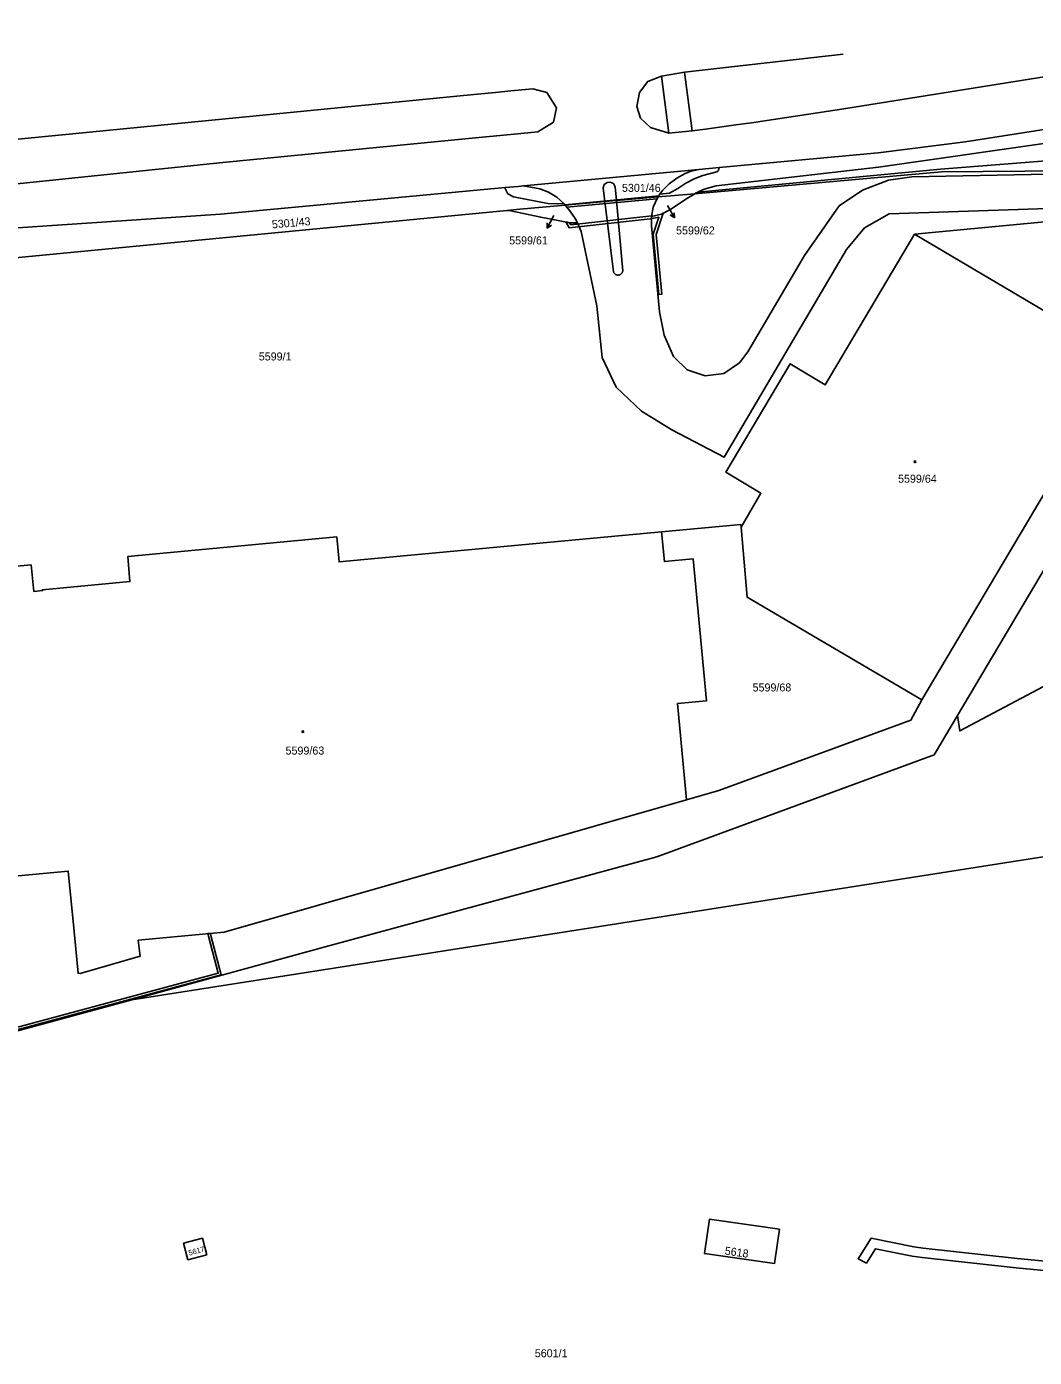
# Model space of a CAD drawing. Extents: x -821458 to -820266, y -1071458 to -1069826.
# Drawn here: x -821204.8 to -820990.7, y -1070118.4 to -1069835.7 of the extents above; entities that cross this region are included whole.
import ezdxf

# ---------------------------------------------------------------- set-up
doc = ezdxf.new("R2010")
doc.units = 0
for name, color, linetype in [('Vrstva 1', 7, 'Continuous'), ('Vrstva 13', 7, 'Continuous'), ('Vrstva 2', 7, 'Continuous'), ('Vrstva 4', 7, 'Continuous'), ('Vrstva 5', 7, 'Continuous'), ('Vrstva 7', 7, 'Continuous')]:
    doc.layers.add(name, color=color, linetype=linetype)

msp = doc.modelspace()

# ---------------------------------------------------------------- linework, layer by layer
at = {"layer": 'Vrstva 1'}
for p, q in [((-821061.99, -1069866.11), (-821099.18, -1069869.56)), ((-821070.6, -1069871.92), (-821070.81, -1069872.22)), ((-821062.78, -1069871.23), (-821070.6, -1069871.92)), ((-821070.6, -1069871.92), (-821070.22, -1069871.36)), ((-821064.36, -1069872.17), (-821062.78, -1069871.23)), ((-821062.78, -1069871.23), (-821062.64, -1069871.14)), ((-821102.76, -1069874.78), (-821099.96, -1069874.51)), ((-821099.96, -1069874.51), (-821090.34, -1069873.66)), ((-821090.34, -1069873.66), (-821090.39, -1069873.6)), ((-821090, -1069874.09), (-821090.34, -1069873.66)), ((-820971.6, -1069906.22), (-821016.17, -1069879.84)), ((-821014.57, -1069978.75), (-820971.6, -1069906.22)), ((-821007, -1069982.04), (-820972.32, -1069923.54)), ((-821182.41, -1070042.44), (-821234.69, -1070056.69))]:
    msp.add_line(p, q, dxfattribs=at)
for points in [[(-821031.28, -1069841.61), (-821065.02, -1069845.45), (-821069.86, -1069846.25), (-821072.8, -1069847.42), (-821074.6, -1069849.74), (-821075.16, -1069852.74), (-821074.35, -1069855.22), (-821072.23, -1069857.2), (-821068.35, -1069858.38), (-821063.36, -1069857.88), (-821060.54, -1069857.49), (-821058.58, -1069857.22), (-821054.1, -1069856.61), (-821050.74, -1069856.15), (-821032.05, -1069853.34), (-821030.77, -1069853.1), (-820959.33, -1069841.72), (-820932.12, -1069837.86), (-820909.53, -1069835.76), (-820877.6, -1069835.74), (-820862.85, -1069836.75)], [(-821061.99, -1069866.11), (-821057.61, -1069865.7), (-821023.88, -1069862.57), (-821005.41, -1069860.19), (-820984.58, -1069856.94), (-820980.88, -1069855.59), (-820969.65, -1069851.52), (-820931.42, -1069845.82), (-820917.79, -1069844.37), (-820894.09, -1069843.23), (-820880.46, -1069843.52), (-820874.49, -1069844.42), (-820869.29, -1069844.79)], [(-821401.79, -1069888.55), (-821396.38, -1069888.03), (-821301.11, -1069878.88), (-821163.06, -1069864.6), (-821108.67, -1069859.31), (-821104.19, -1069858.87), (-821101.19, -1069858.58), (-821096.14, -1069858.08), (-821092.87, -1069856.06), (-821092.18, -1069852.96), (-821094.27, -1069849.73), (-821097.25, -1069848.99), (-821101.9, -1069849.39), (-821105.19, -1069849.71), (-821109.73, -1069850.16), (-821251.45, -1069864.02), (-821303.1, -1069868.83), (-821318.66, -1069870.67)], [(-821062.64, -1069871.14), (-821062.15, -1069870.91), (-821010.61, -1069866.01), (-820904.63, -1069857.69)], [(-820937.16, -1069864.21), (-820966.1, -1069866.2), (-821010.4, -1069866.6), (-821062.78, -1069871.23)], [(-821070.22, -1069871.36), (-821069.67, -1069870.57), (-821068.25, -1069869.11), (-821066.65, -1069867.91), (-821064.88, -1069866.94), (-821063.58, -1069866.45), (-821061.99, -1069866.11)], [(-821099.18, -1069869.56), (-821100.33, -1069869.67), (-821103.12, -1069869.93), (-821163.58, -1069875.55), (-821210.97, -1069878.75)], [(-821090.39, -1069873.6), (-821090.63, -1069873.3), (-821092.16, -1069871.98), (-821093.88, -1069870.91), (-821095.75, -1069870.17), (-821099.18, -1069869.56)], [(-821090.34, -1069873.66), (-821081.94, -1069872.92), (-821079.48, -1069872.7), (-821070.6, -1069871.92)], [(-821070.81, -1069872.22), (-821071.65, -1069874.06), (-821072.01, -1069876.04), (-821069.91, -1069875.59), (-821068.14, -1069874.64), (-821064.36, -1069872.17)], [(-821209.14, -1069885.06), (-821204.97, -1069884.66), (-821102.76, -1069874.78)], [(-821102.76, -1069874.78), (-821101.88, -1069874.89), (-821095.54, -1069876.23), (-821089.29, -1069877.41), (-821087.76, -1069877.41), (-821088.24, -1069876.51), (-821089.38, -1069874.86), (-821090, -1069874.09)], [(-820971.6, -1069906.22), (-820961.64, -1069889.6), (-820963.06, -1069874.82), (-821016.17, -1069879.84)], [(-821016.17, -1069879.84), (-821035.11, -1069911.83), (-821042.56, -1069907.36), (-821056.22, -1069930.41), (-821048.76, -1069934.85), (-821053, -1069942.05)], [(-821069.9, -1069943.03), (-821138.37, -1069949.45), (-821138.89, -1069944.15), (-821183.29, -1069948.31), (-821182.81, -1069953.61), (-821201.39, -1069955.37), (-821201.37, -1069955.54), (-821203.25, -1069955.71), (-821203.8, -1069950.08), (-821242.45, -1069953.67)], [(-821053, -1069942.05), (-821053.05, -1069941.49), (-821069.9, -1069943.03)], [(-821064.55, -1069999.98), (-821066.46, -1069979.54), (-821060.35, -1069978.98), (-821063.18, -1069948.76), (-821069.29, -1069949.37), (-821069.9, -1069943.03)], [(-821053, -1069942.05), (-821051.71, -1069956.95), (-821014.57, -1069978.75)], [(-820943.38, -1069944.62), (-820959, -1069957.1), (-820978.04, -1069970.23), (-821006.55, -1069985.33), (-821007, -1069982.04)], [(-821064.55, -1069999.98), (-821057.7, -1069997.97), (-821016.95, -1069983.03), (-821014.57, -1069978.75)], [(-821007, -1069982.04), (-821011.97, -1069990.43), (-821070.9, -1070012.08), (-821140.56, -1070031.03), (-821182.41, -1070042.44)], [(-821236.96, -1070018.93), (-821195.9, -1070015.13), (-821194.73, -1070027.25), (-821193.83, -1070036.82), (-821193.39, -1070036.85), (-821180.67, -1070033.2), (-821181.06, -1070029.8), (-821162.8, -1070028.08), (-821064.55, -1069999.98)], [(-820956.42, -1070007.02), (-821087.99, -1070027.64), (-821182.41, -1070042.44)], [(-821044.85, -1070091.16), (-821045.87, -1070098.45), (-821060.77, -1070096.38), (-821059.71, -1070089.09), (-821044.85, -1070091.16)], [(-821166.5, -1070096.61), (-821170.51, -1070097.67), (-821171.43, -1070094.17), (-821167.43, -1070093.11), (-821166.5, -1070096.61)]]:
    msp.add_lwpolyline(points, dxfattribs=at)
at = {"layer": 'Vrstva 13'}
for points in [[(-820958.79, -1069866.51), (-821016.72, -1069867.68), (-821021.65, -1069868.36), (-821027.23, -1069870.46), (-821032.16, -1069873.83), (-821039.5, -1069884.34), (-821051.54, -1069904.8), (-821053.33, -1069907.19), (-821056.67, -1069909.43), (-821060.64, -1069909.95), (-821064.46, -1069908.62), (-821067.32, -1069905.83), (-821069.3, -1069901.26), (-821070.32, -1069896.33), (-821072.03, -1069878.08), (-821072.01, -1069876.04), (-821071.65, -1069874.06), (-821070.81, -1069872.22), (-821070.6, -1069871.92), (-821079.48, -1069872.7), (-821081.94, -1069872.92), (-821090.34, -1069873.66), (-821090, -1069874.09), (-821089.38, -1069874.86), (-821088.24, -1069876.51), (-821087.76, -1069877.41), (-821086.99, -1069879.29), (-821083.63, -1069895.03), (-821082.5, -1069906.01), (-821079.54, -1069912.31), (-821074.17, -1069917.44), (-821067.69, -1069921.42), (-821056.58, -1069927.19), (-821030.56, -1069883.07), (-821026.75, -1069878.46), (-821021.5, -1069875.52), (-820964.68, -1069873.6)], [(-821218.16, -1070051.88), (-821163.45, -1070037.13), (-821165.64, -1070028.82), (-821165.76, -1070028.36), (-821166.27, -1070028.41), (-821166.13, -1070028.95), (-821164.06, -1070036.77), (-821218.3, -1070051.4)], [(-820982.38, -1070098.51), (-820994.33, -1070097.43), (-821014.29, -1070095.21), (-821016.32, -1070094.93), (-821025.39, -1070093.11), (-821028.14, -1070097.45), (-821026.37, -1070098.39), (-821024.43, -1070095.35), (-821016.66, -1070096.91), (-821014.53, -1070097.19), (-820994.53, -1070099.41), (-820982.74, -1070100.49)]]:
    msp.add_lwpolyline(points, dxfattribs=at)
for points in [[(-821090.39, -1069873.6), (-821090.34, -1069873.66), (-821090, -1069874.09), (-821070.85, -1069872.3), (-821070.81, -1069872.22), (-821070.6, -1069871.92), (-821070.45, -1069871.7)], [(-821089.15, -1069877.86), (-821089.41, -1069877.39), (-821090.18, -1069877.24), (-821089.49, -1069878.5), (-821072.27, -1069876.54), (-821070.44, -1069876.23), (-821071.64, -1069879.86), (-821070.45, -1069892.65), (-821069.85, -1069892.59), (-821071.03, -1069879.93), (-821069.53, -1069875.39), (-821069.91, -1069875.59), (-821072.01, -1069876.04), (-821071.98, -1069875.9)]]:
    msp.add_lwpolyline(points, close=True, dxfattribs=at)
at = {"layer": 'Vrstva 4'}
for p, q in [((-821069.86, -1069846.25), (-821068.35, -1069858.38)), ((-821065.02, -1069845.45), (-821063.36, -1069857.88)), ((-821023.78, -1069865.56), (-820984.7, -1069860.03)), ((-821061.09, -1069867.38), (-821062.96, -1069868.08)), ((-821058.16, -1069866.58), (-821061.09, -1069867.38)), ((-821058.25, -1069869.59), (-821023.78, -1069865.56)), ((-821057.78, -1069866.33), (-821058.16, -1069866.58)), ((-821057.61, -1069865.7), (-821057.78, -1069866.33)), ((-821103.12, -1069869.93), (-821103.1, -1069870.16)), ((-821103.1, -1069870.16), (-821102.51, -1069871.27)), ((-821082.3, -1069870.01), (-821082.09, -1069869.29)), ((-821081.94, -1069872.92), (-821082.3, -1069870.01)), ((-821082.09, -1069869.29), (-821081.43, -1069868.87)), ((-821081.43, -1069868.87), (-821080.83, -1069868.81)), ((-821080.83, -1069868.81), (-821080.1, -1069869.08)), ((-821080.1, -1069869.08), (-821079.75, -1069869.77)), ((-821079.75, -1069869.77), (-821079.48, -1069872.7)), ((-821066.39, -1069870.11), (-821068.16, -1069871.09)), ((-821064.72, -1069869), (-821066.39, -1069870.11)), ((-821062.96, -1069868.08), (-821064.72, -1069869)), ((-821062.15, -1069870.91), (-821060.81, -1069870.29)), ((-821060.81, -1069870.29), (-821058.25, -1069869.59)), ((-821102.51, -1069871.27), (-821101.36, -1069871.93)), ((-821101.36, -1069871.93), (-821094.03, -1069873.31)), ((-821094.03, -1069873.31), (-821091.99, -1069873.38)), ((-821091.99, -1069873.38), (-821090.63, -1069873.3)), ((-821080.12, -1069887.81), (-821081.94, -1069872.92)), ((-821079.48, -1069872.7), (-821078.12, -1069887.58)), ((-821068.16, -1069871.09), (-821070.22, -1069871.36))]:
    msp.add_line(p, q, dxfattribs=at)
msp.add_lwpolyline([(-821080.12, -1069887.81), (-821080.09, -1069887.89), (-821080.05, -1069887.97), (-821080.01, -1069888.05), (-821079.96, -1069888.12), (-821079.9, -1069888.19), (-821079.84, -1069888.25), (-821079.77, -1069888.31), (-821079.7, -1069888.36), (-821079.62, -1069888.4), (-821079.54, -1069888.44), (-821079.46, -1069888.47), (-821079.38, -1069888.5), (-821079.29, -1069888.51), (-821079.2, -1069888.52), (-821079.11, -1069888.52), (-821079.03, -1069888.52), (-821078.94, -1069888.5), (-821078.85, -1069888.48), (-821078.77, -1069888.45), (-821078.69, -1069888.42), (-821078.61, -1069888.37), (-821078.54, -1069888.33), (-821078.47, -1069888.27), (-821078.41, -1069888.21), (-821078.35, -1069888.14), (-821078.29, -1069888.07), (-821078.25, -1069888), (-821078.21, -1069887.92), (-821078.18, -1069887.84), (-821078.15, -1069887.75), (-821078.13, -1069887.67), (-821078.12, -1069887.58)], dxfattribs=at)
at = {"layer": 'Vrstva 5'}
for centre in [(-821016.03, -1069928.18), (-821146.08, -1069985.49)]:
    msp.add_circle(centre, 0.175, dxfattribs=at)
at = {"layer": 'Vrstva 7'}
for p, q in [((-821092.75, -1069875.89), (-821094.21, -1069878.52)), ((-821068.6, -1069873.76), (-821067.15, -1069876.39)), ((-821067.15, -1069876.39), (-821068.07, -1069875.75)), ((-821067.15, -1069876.39), (-821067.19, -1069875.27)), ((-821094.21, -1069878.52), (-821094.16, -1069877.4)), ((-821094.21, -1069878.52), (-821093.28, -1069877.88))]:
    msp.add_line(p, q, dxfattribs=at)

# ---------------------------------------------------------------- texts
at = {"layer": 'Vrstva 2'}
for s, p in [('5301/46', (-821078.29, -1069870.84)), ('5599/62', (-821066.8, -1069879.88)), ('5599/61', (-821102.25, -1069882)), ('5599/1', (-821155.44, -1069906.65)), ('5599/64', (-821019.64, -1069932.62)), ('5599/68', (-821050.54, -1069976.96)), ('5599/63', (-821149.75, -1069990.37)), ('5601/1', (-821096.81, -1070118.39))]:
    msp.add_text(s, height=1.7, dxfattribs=at).set_placement(p)
for s, height, rotation, p in [('5301/43', 1.7, 5, (-821152.58, -1069878.62)), ('5617', 1.139, 15, (-821170.21, -1070096.81)), ('5618', 1.7, 352, (-821056.54, -1070096.56))]:
    msp.add_text(s, height=height, rotation=rotation, dxfattribs=at).set_placement(p)

doc.saveas('drawing.dxf')
